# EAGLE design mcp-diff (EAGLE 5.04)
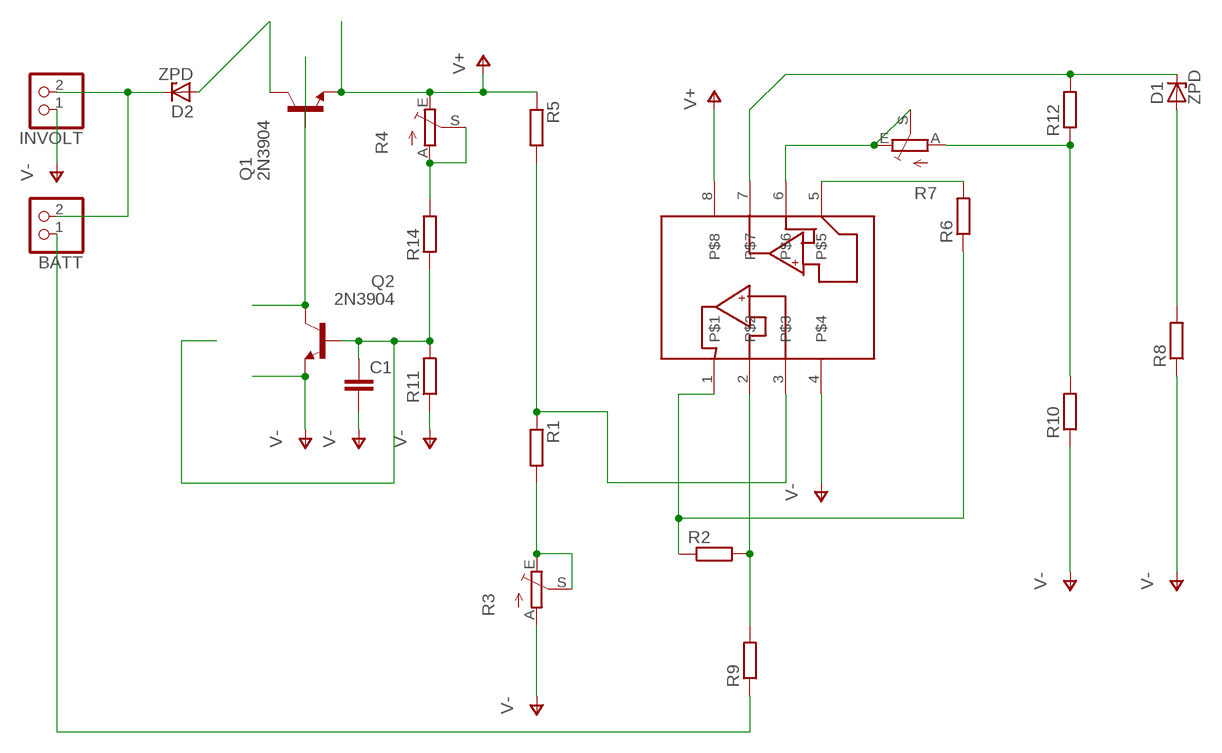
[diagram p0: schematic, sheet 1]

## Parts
BATT  PINHD-1X2  [1X02]
C1  C-EU050-024X044  [C050-024X044]
D1  ZPD  [DO35Z10]
D2  ZPD  [DO35Z10]
INVOLT  PINHD-1X2  [1X02]
Q1  2N3904  [TO92]
Q2  2N3904  [TO92]
R1  R-EU_0207/15  [0207/15]
R2  R-EU_0207/15  [0207/15]
R3  TRIM_EU-LI15  [LI15]
R4  TRIM_EU-LI15  [LI15]
R5  R-EU_0207/15  [0207/15]
R6  R-EU_0207/15  [0207/15]
R7  TRIM_EU-LI15  [LI15]
R8  R-EU_0207/15  [0207/15]
R9  R-EU_0207/15  [0207/15]
R10  R-EU_0207/15  [0207/15]
R11  R-EU_0207/10  [0207/10]
R12  R-EU_0207/15  [0207/15]
R14  R-EU_0207/10  [0207/10]
U$1  MCP6042SOIC  [SO-08]

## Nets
N$1: D1.C R12.2 U$1.7
N$2: R7.E R7.S U$1.6
N$3: Q1.2(B) Q2.1(C)
N$4: R4.A R4.S R14.2
N$5: R6.2 U$1.5
N$6: D2.A Q1.1(C)
N$7: R2.2 R9.2 U$1.2
N$8: BATT.2 D2.C INVOLT.2
N$9: C1.1 Q2.2(B) R11.2 R14.1
N$11: R1.1 R5.2 U$1.3
N$12: BATT.1 R9.1
N$13: R2.1 R6.1 U$1.1
N$14: R1.2 R3.E R3.S
N$15: D1.A R8.2
N$16: R7.A R10.2 R12.1
V+: Q1.3(E) R4.E R5.1 U$1.8
V-: C1.2 INVOLT.1 Q2.3(E) R3.A R8.1 R10.1 R11.1 U$1.4

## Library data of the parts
BATT INVOLT = pinhead:PINHD-1X2: PIN HEADER
C1 = rcl:C-EU: CAPACITOR, European symbol
D1 D2 = diode:ZPD: Z DIODE
Q1 Q2 = transistor-npn:2N3904: NPN Transistor
R1 R2 R5 R6 R8-R10 R12 = rcl:R-EU_: RESISTOR, European symbol
R3 R4 R7 = pot:TRIM_EU-: POTENTIOMETER
R11 R14 = rcl-2:R-EU_: RESISTOR, European symbol
U$1 = microchip-3:MCP6042

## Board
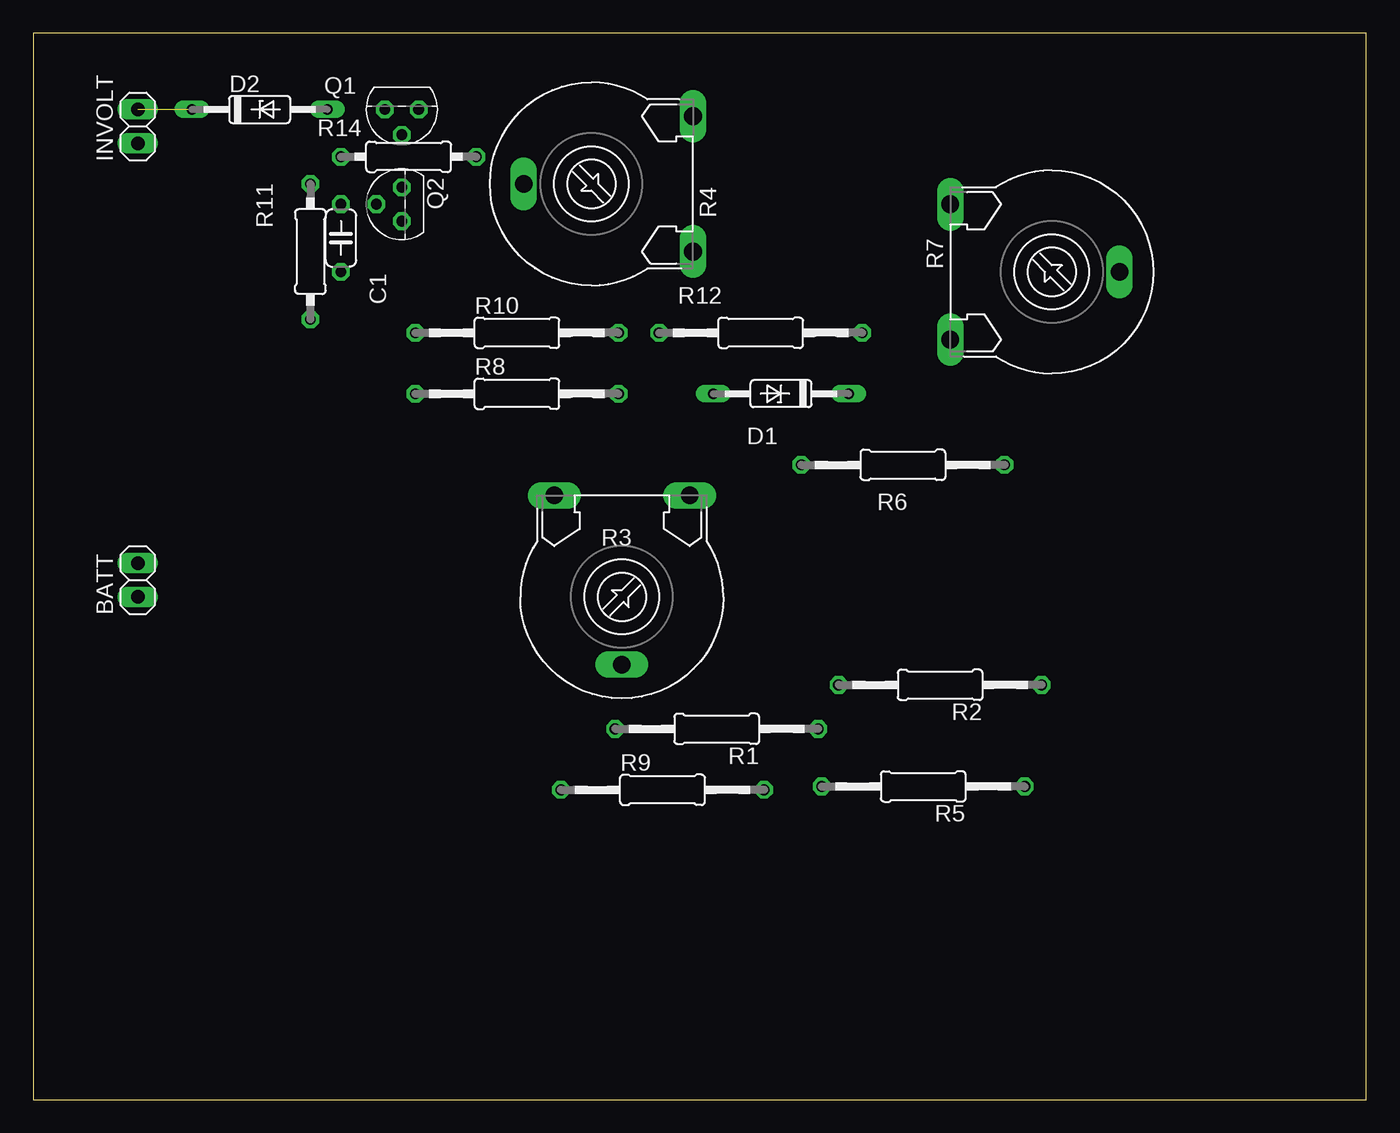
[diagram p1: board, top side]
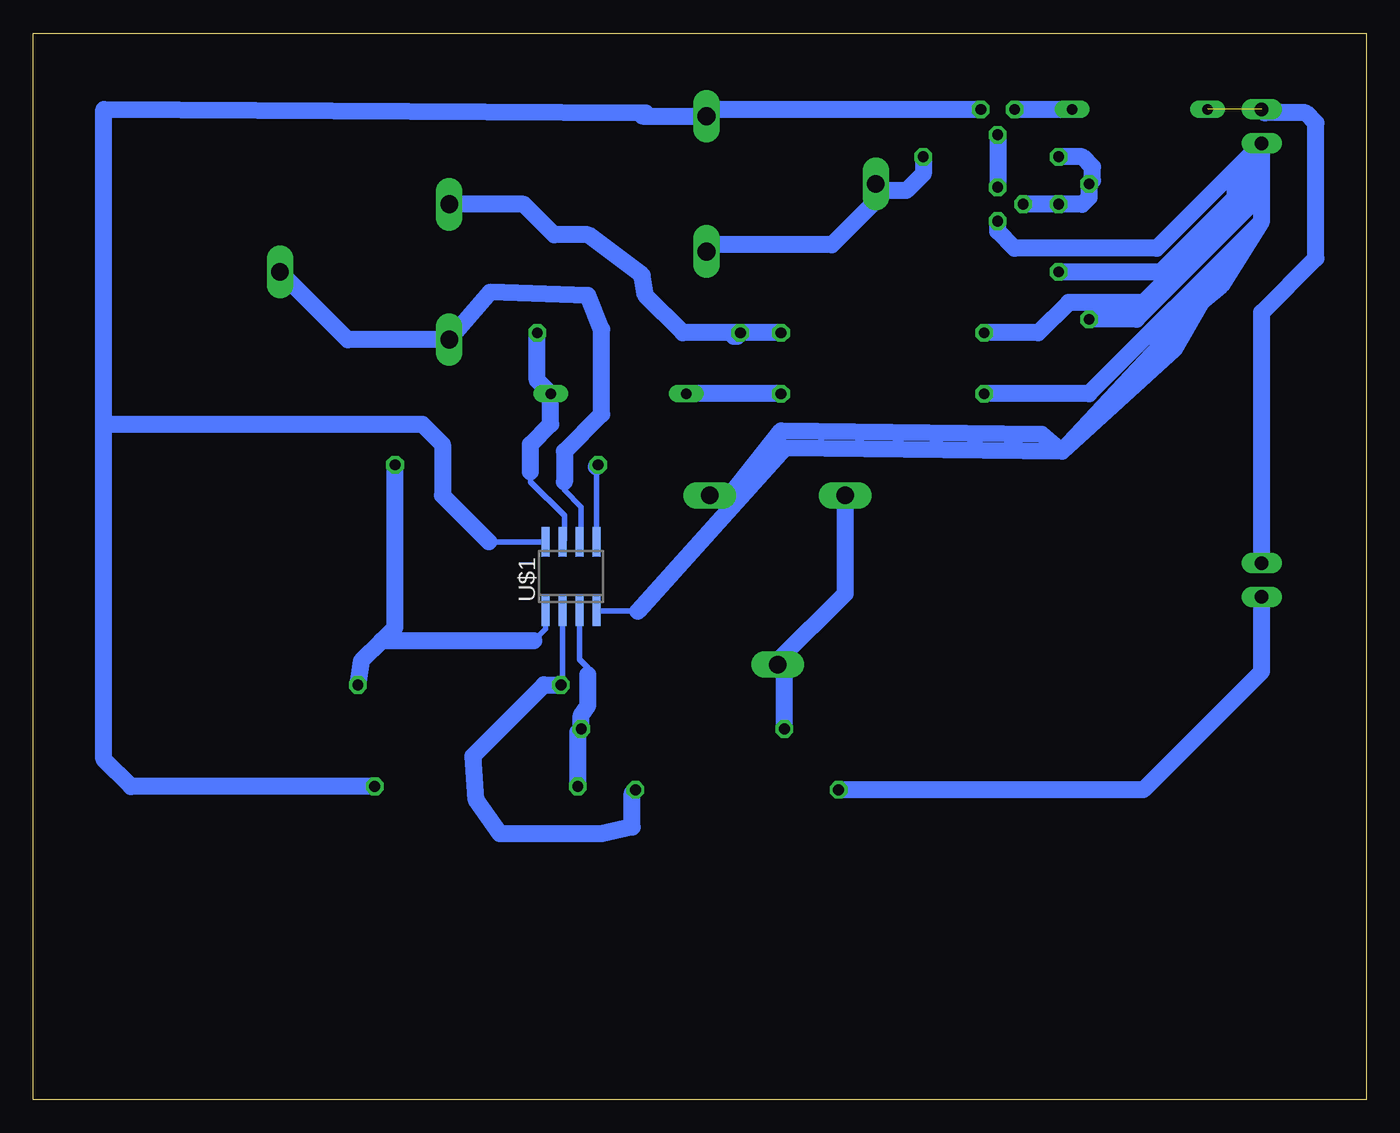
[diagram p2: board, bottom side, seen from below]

Size 100 x 80 mm. Coordinates in mm from the lower left corner, seen from the top.
Outline: 0,0 100,0 100,80 0,80 0,0
Copper layers (1*16): Top 0.035mm / dielectric 1.5mm / Bottom 0.035mm
Design rules "default": minimum track width 20mil, minimum drill 24mil, track to track 20mil, track to pad 20mil, pad to pad 8mil, via to via 8mil, smd to smd 8mil, copper to edge 40mil, drill to drill 8mil, minimum pad ring 10mil, minimum via ring 8mil, stop-mask expansion 4mil, vias tented up to drill 0mil, thermal gap 10mil

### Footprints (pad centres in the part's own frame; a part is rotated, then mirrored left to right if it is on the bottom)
1X02 = drill 1.016 long: 1 -1.27,0; 2 1.27,0
C050-024X044 = drill 0.813 octagon: 1 -2.54,0; 2 2.54,0
DO35Z10 = drill 0.813 long: A 5.08,0; C -5.08,0
TO92 = drill 0.813 octagon: 1 1.27,0; 2 0,1.905; 3 -1.27,0
0207/15 = drill 0.813 octagon: 1 -7.62,0; 2 7.62,0
LI15 = drill 1.321 long: A -5.08,-7.62; E 5.08,-7.62; S 0,5.08
0207/10 = drill 0.813 octagon: 1 -5.08,0; 2 5.08,0
SO-08 = smd 0.6 x 2.2: 1 -1.905,-2.6; 2 -0.635,-2.6; 3 0.635,-2.6; 4 1.905,-2.6; 5 1.905,2.6; 6 0.635,2.6; 7 -0.635,2.6; 8 -1.905,2.6

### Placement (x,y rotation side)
BATT  7.84,38.98 90 top
C1  23.08,64.64 270 top
D1  56.1,52.95 180 top
D2  16.98,74.29 0 top
INVOLT  7.84,73.02 90 top
Q1  27.65,74.29 180 top
Q2  27.65,67.18 90 top
R1  51.27,27.81 180 top
R2  68.03,31.11 180 top
R3  44.16,37.71 180 top
R4  41.87,68.7 90 top
R5  66.76,23.49 180 top
R6  65.24,47.62 180 top
R7  76.42,62.1 270 top
R8  36.28,52.95 0 top
R9  47.21,23.24 0 top
R10  36.28,57.53 0 top
R11  20.79,63.62 90 top
R12  54.57,57.53 0 top
R14  28.16,70.73 0 top
U$1  59.65,39.24 0 bottom

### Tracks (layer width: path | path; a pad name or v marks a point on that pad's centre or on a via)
N$1
  Bottom 0.406: 62.7,47.11 62.7,46.35 60.16,43.81 60.16,41.97 U$1.7
  Bottom 1.27: R12.2 62.19,53.97 D1.C 61.18,50.67 62.7,49.14 62.7,47.11
N$2
  Bottom 0.406: 60.16,46.35 60.16,45.72 58.89,44.45 58.89,41.97 U$1.6
  Bottom 1.27: 60.16,46.35 60.16,48.64 57.37,51.43 57.37,57.78 58.38,60.32 65.75,60.57 R7.E 76.42,57.02 R7.S
N$3
  Bottom 1.27: Q1.2 Q2.1
N$4
  Bottom 1.27: R14.2 33.24,69.46 34.51,68.19 36.28,68.19 R4.S 36.79,67.43 40.09,64.13 48.98,64.13 R4.A
N$5
  Bottom 0.406: 57.75,47.49 U$1.5
  Bottom 1.27: R6.2 57.75,47.49
N$6
  Bottom 1.27: Q1.1 D2.A
N$7
  Bottom 0.406: U$1.2 60.29,31.24 R2.2
  Bottom 1.27: R2.2 61.68,31.11 67.02,25.78 66.76,22.47 64.99,19.93 57.37,19.93 55.08,20.44 55.08,22.98 R9.2
N$8  (1 unrouted)
  Bottom 1.27: BATT.2 7.84,59.05 3.77,63.11 3.77,73.27 4.53,74.04 7.58,74.04 INVOLT.2
N$9
  Bottom 1.27: R14.1 21.3,70.73 20.54,69.97 20.54,68.96 R11.2 20.79,67.69 21.3,67.18 C1.1 Q2.2
N$11
  Bottom 0.406: U$1.3 59.02,33.02 58.38,32.38 58.38,31.87
  Bottom 1.27: R5.2 59.14,27.55 R1.1 58.89,28.82 58.38,29.59 58.38,31.87
N$12
  Bottom 1.27: R9.1 16.73,23.24 7.84,32.13 BATT.1
N$13
  Bottom 0.406: U$1.1 61.56,35.3 62.45,34.41
  Bottom 1.27: R2.1 75.4,32.89 73.88,34.41 | 62.45,34.41 73.88,34.41 | R6.1 72.86,35.43 73.88,34.41
N$14
  Bottom 1.27: R1.2 43.65,32.13 R3.S 44.16,32.89 39.08,37.97 R3.E
N$15
  Bottom 1.27: R8.2 D1.A
N$16
  Bottom 1.27: R10.2 R12.1 | R12.1 47.21,57.53 47.46,57.27 47.21,57.27 R12.1 | R12.1 51.27,57.53 54.06,60.32 54.32,61.84 58.38,64.89 60.92,64.89 63.21,67.18 R7.A
V+
  Bottom 0.406: U$1.8 65.81,41.84
  Bottom 1.27: R5.1 92.67,23.49 94.7,25.52 94.7,50.41 | 94.7,50.41 94.7,74.29 54.57,74.04 | 54.57,74.04 54.06,74.04 | 65.81,41.84 69.3,45.33 69.3,49.14 70.83,50.67 94.45,50.67 94.7,50.41 | Q1.3 48.98,74.29 R4.E 54.31,73.78 54.57,74.04
V-
  Bottom 0.406: U$1.4 54.63,36.64
  Bottom 1.27: R11.1 17.23,58.54 8.34,67.43 8.34,71.24 | 8.34,71.24 INVOLT.1 7.84,65.91 | C1.2 15.46,62.1 9.87,67.69 9.87,69.72 | 8.34,71.24 8.6,70.99 | 8.6,70.99 9.87,69.72 | Q2.3 27.65,65.15 26.38,63.88 15.71,63.88 9.87,69.72 | R10.1 24.6,57.53 22.31,59.81 16.73,59.81 9.36,67.18 9.36,70.23 8.6,70.99 | R8.1 20.79,52.95 7.84,65.91 | R3.A 47.71,45.33 43.9,50.16 24.35,49.91 22.82,48.64 | 12.41,59.81 22.82,48.64 | 12.41,59.81 10.88,61.08 7.84,65.91 | 54.63,36.64 43.65,48.89 22.82,48.64 | 22.82,48.64 14.44,56.26 12.41,59.81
